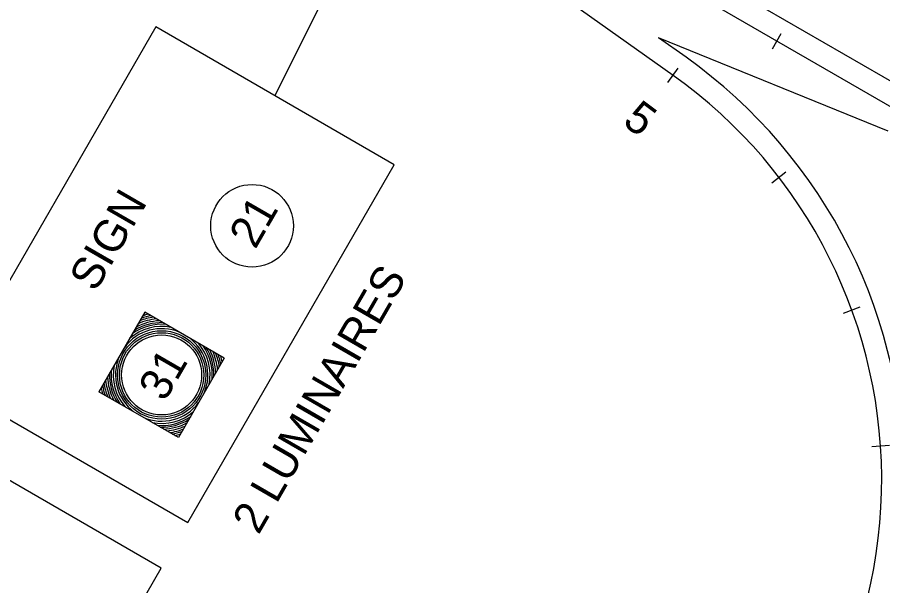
# Model space of a CAD drawing. Extents: x 36 to 2622, y -5330 to 219.
# Drawn here: x 388.5 to 469.4, y -5062 to -5008.9 of the extents above; entities that cross this region are included whole.
import ezdxf

# ---------------------------------------------------------------- set-up
doc = ezdxf.new("R2010")
doc.units = 0
doc.layers.add('2', color=7, linetype='Continuous')

msp = doc.modelspace()

# ---------------------------------------------------------------- linework, layer by layer
at = {"layer": '2'}
for p, q in [((693.9, -5144.068), (416.962, -4984.173)), ((692.86, -5145.872), (414.78, -4985.319)), ((449.796, -5014.336), (411.322, -4987.004)), ((412.57, -5016.246), (426.518, -4988.379)), ((459.074, -5011.85), (459.899, -5010.417)), ((469.913, -5019.557), (448.437, -5010.82)), ((451, -5012.641), (448.437, -5010.82)), ((449.315, -5015.012), (450.276, -5013.66)), ((459.03, -5024.365), (460.34, -5023.347)), ((465.726, -5036.557), (467.28, -5035.976)), ((470.019, -5048.932), (468.364, -5049.048))]:
    msp.add_line(p, q, dxfattribs=at)
for points in [[(404.412, -5056.123), (423.718, -5022.682), (401.425, -5009.81), (382.118, -5043.251)], [(382.636, -5093.835), (401.943, -5060.394), (379.649, -5047.522), (360.343, -5080.963)]]:
    msp.add_lwpolyline(points, close=True, dxfattribs=at)
for points in [[(400.403, -5036.461), (396.112, -5043.892)], [(407.834, -5040.751), (400.403, -5036.461)], [(407.834, -5040.751), (403.542, -5048.183)], [(403.542, -5048.183), (396.112, -5043.892)]]:
    msp.add_lwpolyline(points, dxfattribs=at)
for centre, radius in [((410.43, -5028.388), 3.861), ((401.977, -5042.321), 4.125), ((401.977, -5042.321), 3.945), ((401.977, -5042.321), 3.739)]:
    msp.add_circle(centre, radius, dxfattribs=at)
for centre, radius, start, end in [((422.958, -5052.113), 48.42, 302.50872, 54.60763), ((422.958, -5052.113), 46.34, 302.50872, 54.60763), ((401.977, -5042.321), 5.062, 92.10219, 117.9954), ((401.977, -5042.321), 5.257, 95.33768, 114.74865), ((401.977, -5042.321), 5.445, 98.04142, 112.0368), ((401.977, -5042.321), 5.617, 100.23096, 109.84137), ((401.977, -5042.321), 5.796, 102.28011, 107.78718), ((401.977, -5042.321), 4.319, 66.90383, 143.62104), ((401.977, -5042.321), 4.529, 78.77474, 131.40598), ((401.977, -5042.321), 4.73, 84.96904, 125.16259), ((401.977, -5042.321), 4.884, 88.60357, 121.50876), ((401.977, -5042.321), 4.319, 336.90383, 53.09616), ((401.977, -5042.321), 4.529, 348.77474, 41.22526), ((401.977, -5042.321), 4.73, 354.96904, 35.03095), ((401.977, -5042.321), 4.884, 358.60357, 31.39642), ((401.977, -5042.321), 5.062, 2.10219, 27.8978), ((401.977, -5042.321), 5.257, 5.33768, 24.66231), ((401.977, -5042.321), 5.445, 8.04142, 21.95858), ((401.977, -5042.321), 5.617, 10.23096, 19.76903), ((401.977, -5042.321), 4.319, 156.37895, 233.62104), ((401.977, -5042.321), 5.796, 12.28011, 17.71989), ((401.977, -5042.321), 4.73, 174.8374, 215.16259), ((401.977, -5042.321), 4.529, 168.59402, 221.40597), ((401.977, -5042.321), 5.257, 185.25134, 204.74864), ((401.977, -5042.321), 5.062, 182.00459, 207.9954), ((401.977, -5042.321), 4.884, 178.49123, 211.50876), ((401.977, -5042.321), 5.796, 192.21282, 197.78717), ((401.977, -5042.321), 5.617, 190.15863, 199.84136), ((401.977, -5042.321), 5.445, 187.9632, 202.03679), ((401.977, -5042.321), 4.319, 246.37895, 323.09616), ((401.977, -5042.321), 4.529, 258.59402, 311.22526), ((401.977, -5042.321), 4.73, 264.8374, 305.03096), ((401.977, -5042.321), 4.884, 268.49123, 301.39643), ((401.977, -5042.321), 5.062, 272.00459, 297.8978), ((401.977, -5042.321), 5.257, 275.25134, 294.66232), ((401.977, -5042.321), 5.445, 277.9632, 291.95858), ((401.977, -5042.321), 5.617, 280.15863, 289.76903), ((401.977, -5042.321), 5.796, 282.21282, 287.71989)]:
    msp.add_arc(centre, radius, start, end, dxfattribs=at)

# ---------------------------------------------------------------- texts
for s, height, rotation, p in [('5', 2.996, 322.98852, (444.959, -5018.86)), ('SIGN', 2.9955, 60, (395.793, -5034.672)), ('21', 2.9955, 60, (410.729, -5030.663)), ('2 LUMINAIRES', 2.9955, 60, (411.037, -5057.334)), ('31', 2.9955, 60, (402.261, -5044.919))]:
    msp.add_text(s, height=height, rotation=rotation, dxfattribs=at).set_placement(p)

doc.saveas('drawing.dxf')
